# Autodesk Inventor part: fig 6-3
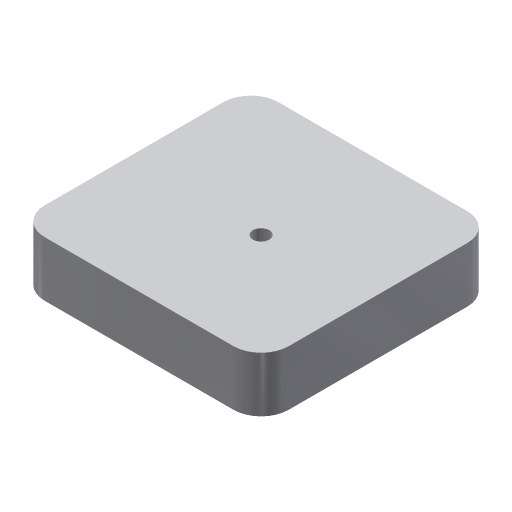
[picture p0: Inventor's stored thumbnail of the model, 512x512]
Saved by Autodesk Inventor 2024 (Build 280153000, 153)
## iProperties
Created: 2004-05
Part Number: fig 6-3
Document SubType Name: Modeling
Designer: CADCIM Technologies
Manufacturer: Standard
Standards Organization: Custom
Density: 1 g/cm^3
Material: Generic
Appearance: Default
Author: CADCIM Technologies
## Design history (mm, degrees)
sketch "Sketch1"
  geometry: L1 (0, 0)-(44.293, 0); L2 (44.293, 0)-(44.293, 42.442); L3 (44.293, 42.442)-(0, 42.442); L4 (0, 42.442)-(0, 0)
  constraints: 8 end point, 2 parallel, 1 horizontal, 1 perpendicular
extrude "Extrusion1" new body sketch "Sketch1" distance "d0" = 10; taper "d1" = 0 deg
fillet "Fillet1" dims "d2" = 5
hole "Hole1" diameter "d6" = 3; stored, may be unused: countersink angle "d10" = 90 deg, drill point angle "d12" = 118 deg; dims "d4" = 20, "d5" = 20, "d7" = 6, "d8" = 4, "d9" = 2, "d11" = 8
body "Solid1"
